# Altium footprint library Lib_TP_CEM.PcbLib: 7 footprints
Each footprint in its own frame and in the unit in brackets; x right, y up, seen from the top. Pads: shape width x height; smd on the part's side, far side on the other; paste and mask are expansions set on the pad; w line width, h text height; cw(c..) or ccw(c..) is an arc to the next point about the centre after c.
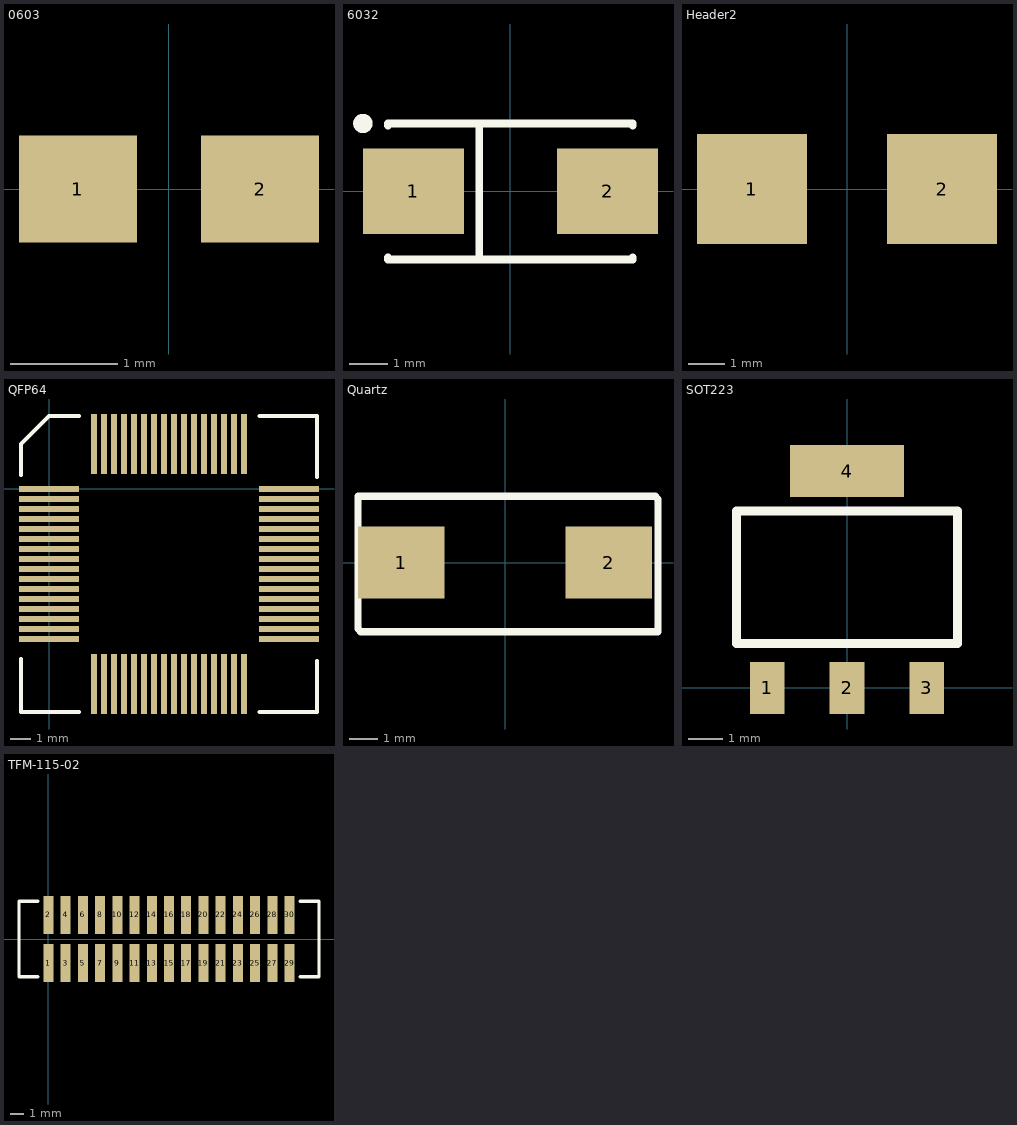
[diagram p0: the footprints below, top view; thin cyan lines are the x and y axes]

## 0603 [mm] "Chip Capacitor; Body 1.6 x 0.8 mm (LxW typ)"
height 1.35
pads (2):
  rect 1.1x1 smd: 1(-0.85,0) 2(0.85,0)

## 6032 [mm] "Capacitor, SM Tantalum; Body 6.0 x 3.2 mm (LxW typ)"
height 2.8
pads (2):
  rect 2.6x2.2 smd: 1(-2.5,0) 2(2.5,0)
Top Overlay:
  circle w0.25: c-3.8,1.75 r0.125
  lines w0.2: -3.15,-1.7 -3.15,-1.75 3.15,-1.75 3.15,-1.7 ; -3.15,1.7 -3.15,1.75 3.15,1.75 3.15,1.7 ; -0.8,-1.75 -0.8,1.75

## Header2 [mm]
pads (2):
  rect 3x3 smd: 1(-2.6,0) 2(2.6,0)

## QFP64 [mm] "STARCORE package"
pads (64):
  rect 3x0.3 smd: 1(0,0) 2(0,-0.5) 3(0,-1) 4(0,-1.5) 5(0,-2) 6(0,-2.5) 7(0,-3) 8(0,-3.5) 9(0,-4) 10(0,-4.5) 11(0,-5) 12(0,-5.5) 13(0,-6) 14(0,-6.5) 15(0,-7) 16(0,-7.5) 33(11.97,-7.5) 34(11.97,-7) 35(11.97,-6.5) 36(11.97,-6) 37(11.97,-5.5) 38(11.97,-5) 39(11.97,-4.5) 40(11.97,-4) 41(11.97,-3.5) 42(11.97,-3) 43(11.97,-2.5) 44(11.97,-2) 45(11.97,-1.5) 46(11.97,-1) 47(11.97,-0.5) 48(11.97,0)
  rect 0.3x3 smd: 17(2.235,-9.735) 18(2.735,-9.735) 19(3.235,-9.735) 20(3.735,-9.735) 21(4.235,-9.735) 22(4.735,-9.735) 23(5.235,-9.735) 24(5.735,-9.735) 25(6.235,-9.735) 26(6.735,-9.735) 27(7.235,-9.735) 28(7.735,-9.735) 29(8.235,-9.735) 30(8.735,-9.735) 31(9.235,-9.735) 32(9.735,-9.735) 49(9.735,2.235) 50(9.235,2.235) 51(8.735,2.235) 52(8.235,2.235) 53(7.735,2.235) 54(7.235,2.235) 55(6.735,2.235) 56(6.235,2.235) 57(5.735,2.235) 58(5.235,2.235) 59(4.735,2.235) 60(4.235,2.235) 61(3.735,2.235) 62(3.235,2.235) 63(2.735,2.235) 64(2.235,2.235)
Top Overlay:
  lines w0.2: -1.4,-8.5 -1.4,-11.135 1.5,-11.135 ; -1.4,0.7 -1.4,2.235 0,3.635 1.5,3.635 ; 10.5,-11.135 13.37,-11.135 13.37,-8.6 ; 10.5,3.635 13.37,3.635 13.37,0.6

## Quartz [mm]
pads (2):
  rect 3x2.5 smd: 1(-3.6,0) 2(3.6,0)
Top Overlay:
  lines w0.254: -5.1,-2.3 -5.1,2.3 5.2,2.3 5.3,2.2 5.3,-2.4 -5,-2.4 -5.1,-2.3

## SOT223 [mil] "SOT223"
pads (4):
  rect 39x59 smd: 1(-90,0) 2(0,0) 3(90,0)
  rect 129x59 smd: 4(0,245)
Top Overlay:
  lines w10: -125,50 -125,200 125,200 125,50 -125,50

## TFM-115-02 [mil]
pads (30):
  rect 29x110 smd: 1(0,-70) 2(0,70) 3(50,-70) 4(50,70) 5(100,-70) 6(100,70) 7(150,-70) 8(150,70) 9(200,-70) 10(200,70) 11(250,-70) 12(250,70) 13(300,-70) 14(300,70) 15(350,-70) 16(350,70) 17(400,-70) 18(400,70) 19(450,-70) 20(450,70) 21(500,-70) 22(500,70) 23(550,-70) 24(550,70) 25(600,-70) 26(600,70) 27(650,-70) 28(650,70) 29(700,-70) 30(700,70)
Top Overlay:
  lines w10: -30,-110 -85,-110 -85,110 -30,110 ; 730,-110 785,-110 785,110 730,110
